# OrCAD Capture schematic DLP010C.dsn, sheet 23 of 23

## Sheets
23 PAGE 22 - UNUSED PINS: size Custom
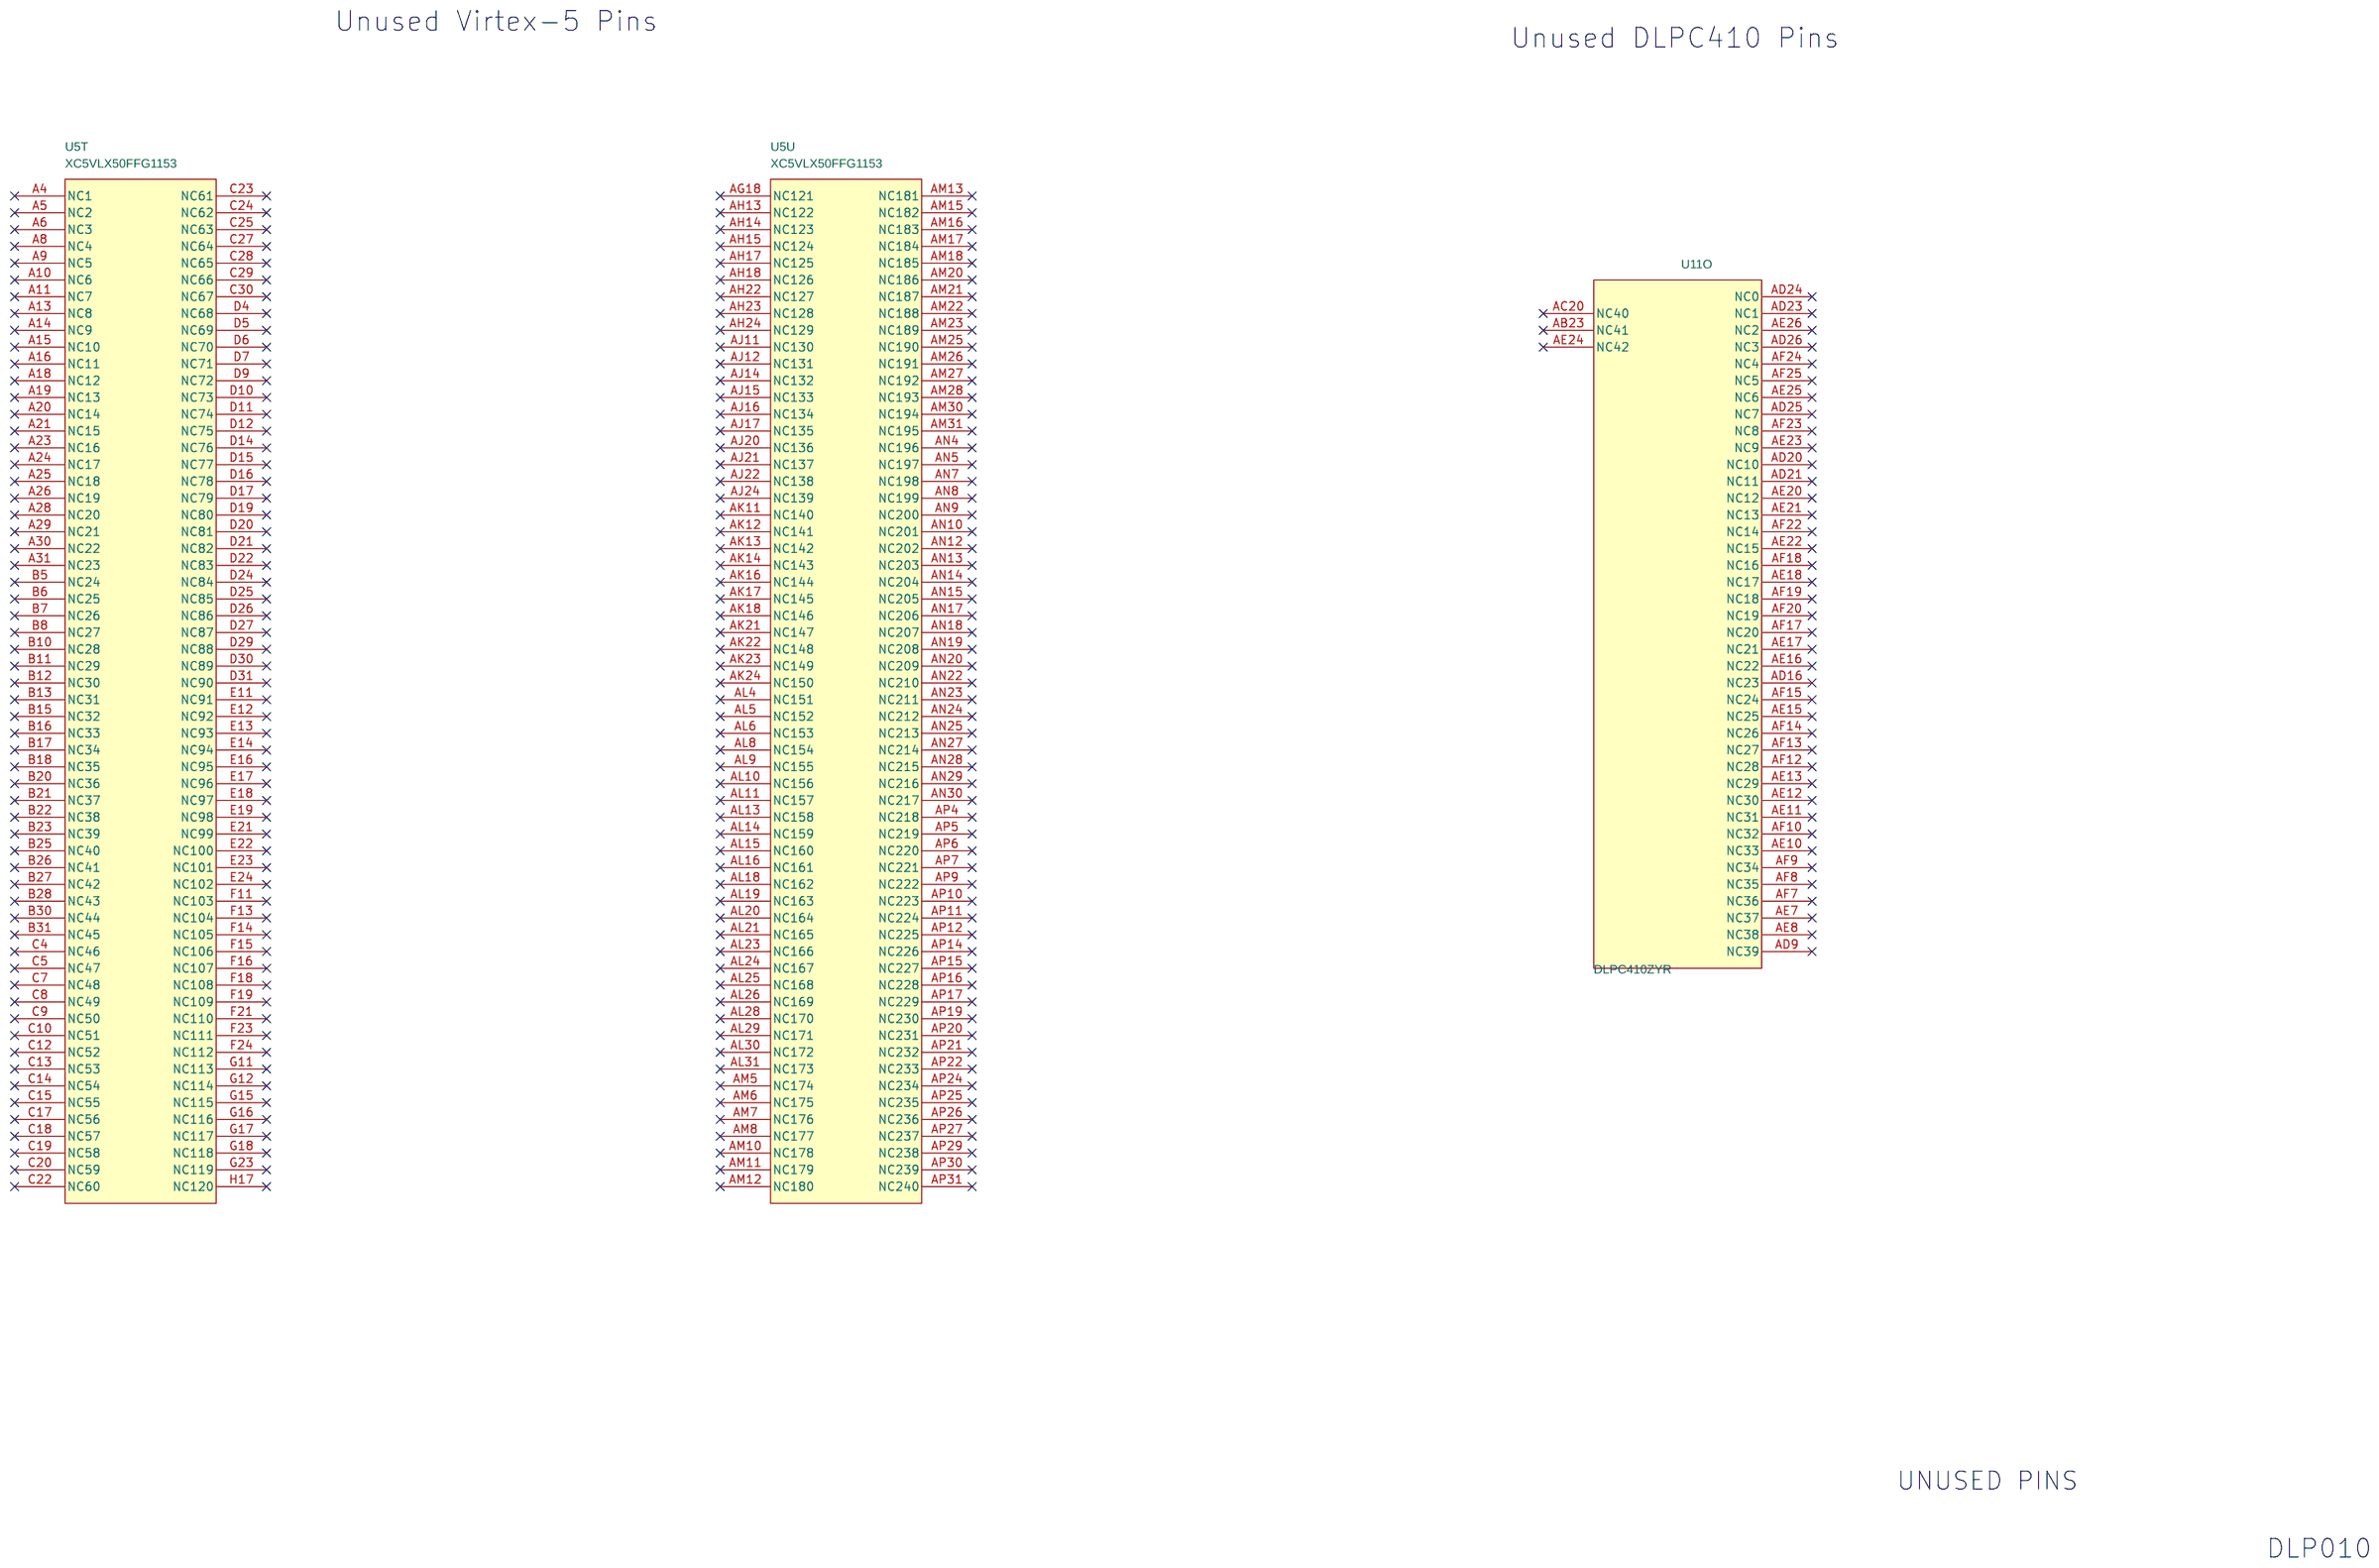
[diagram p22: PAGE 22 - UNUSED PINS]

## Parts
sheet PAGE 07 - VIRTEX5 - 4
U5  XC5VLX50FFG1153  [sm_ff1153]  (sections A,B,C,D,E,F,G,H,I,J,K,L,M,N,O,P,Q,R,S,T,U)
sheet PAGE 10 - DLPC410 - 2
U11  DLPC410ZYR  [sm_ff676]  (sections A,B,C,D,E,F,G,H,I,J,K,L,M,N,O)

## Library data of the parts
U5 = XC5VLX50FF1153_13: Manuf: xilinx; PartNumber: XC5VLX50-1FFG1153C; ROOM: V5
U11 = XC5VLX30FF676: Manuf: Texas Instruments; ROOM: DDC4100

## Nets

Not connected (* = marked no-connect by the designer): U5 A4(NC1)* A5(NC2)* A6(NC3)* A8(NC4)* A9(NC5)* A10(NC6)* A11(NC7)* A13(NC8)* A14(NC9)* A15(NC10)* A16(NC11)* A18(NC12)* A19(NC13)* A20(NC14)* A21(NC15)* A23(NC16)* A24(NC17)* A25(NC18)* A26(NC19)* A28(NC20)* A29(NC21)* A30(NC22)* A31(NC23)* AG18(NC121)* AH13(NC122)* AH14(NC123)* AH15(NC124)* AH17(NC125)* AH18(NC126)* AH22(NC127)* AH23(NC128)* AH24(NC129)* AJ11(NC130)* AJ12(NC131)* AJ14(NC132)* AJ15(NC133)* AJ16(NC134)* AJ17(NC135)* AJ20(NC136)* AJ21(NC137)* AJ22(NC138)* AJ24(NC139)* AK11(NC140)* AK12(NC141)* AK13(NC142)* AK14(NC143)* AK16(NC144)* AK17(NC145)* AK18(NC146)* AK21(NC147)* AK22(NC148)* AK23(NC149)* AK24(NC150)* AL4(NC151)* AL5(NC152)* AL6(NC153)* AL8(NC154)* AL9(NC155)* AL10(NC156)* AL11(NC157)* AL13(NC158)* AL14(NC159)* AL15(NC160)* AL16(NC161)* AL18(NC162)* AL19(NC163)* AL20(NC164)* AL21(NC165)* AL23(NC166)* AL24(NC167)* AL25(NC168)* AL26(NC169)* AL28(NC170)* AL29(NC171)* AL30(NC172)* AL31(NC173)* AM5(NC174)* AM6(NC175)* AM7(NC176)* AM8(NC177)* AM10(NC178)* AM11(NC179)* AM12(NC180)* AM13(NC181)* AM15(NC182)* AM16(NC183)* AM17(NC184)* AM18(NC185)* AM20(NC186)* AM21(NC187)* AM22(NC188)* AM23(NC189)* AM25(NC190)* AM26(NC191)* AM27(NC192)* AM28(NC193)* AM30(NC194)* AM31(NC195)* AN4(NC196)* AN5(NC197)* AN7(NC198)* AN8(NC199)* AN9(NC200)* AN10(NC201)* AN12(NC202)* AN13(NC203)* AN14(NC204)* AN15(NC205)* AN17(NC206)* AN18(NC207)* AN19(NC208)* AN20(NC209)* AN22(NC210)* AN23(NC211)* AN24(NC212)* AN25(NC213)* AN27(NC214)* AN28(NC215)* AN29(NC216)* AN30(NC217)* AP4(NC218)* AP5(NC219)* AP6(NC220)* AP7(NC221)* AP9(NC222)* AP10(NC223)* AP11(NC224)* AP12(NC225)* AP14(NC226)* AP15(NC227)* AP16(NC228)* AP17(NC229)* AP19(NC230)* AP20(NC231)* AP21(NC232)* AP22(NC233)* AP24(NC234)* AP25(NC235)* AP26(NC236)* AP27(NC237)* AP29(NC238)* AP30(NC239)* AP31(NC240)* B5(NC24)* B6(NC25)* B7(NC26)* B8(NC27)* B10(NC28)* B11(NC29)* B12(NC30)* B13(NC31)* B15(NC32)* B16(NC33)* B17(NC34)* B18(NC35)* B20(NC36)* B21(NC37)* B22(NC38)* B23(NC39)* B25(NC40)* B26(NC41)* B27(NC42)* B28(NC43)* B30(NC44)* B31(NC45)* C4(NC46)* C5(NC47)* C7(NC48)* C8(NC49)* C9(NC50)* C10(NC51)* C12(NC52)* C13(NC53)* C14(NC54)* C15(NC55)* C17(NC56)* C18(NC57)* C19(NC58)* C20(NC59)* C22(NC60)* C23(NC61)* C24(NC62)* C25(NC63)* C27(NC64)* C28(NC65)* C29(NC66)* C30(NC67)* D4(NC68)* D5(NC69)* D6(NC70)* D7(NC71)* D9(NC72)* D10(NC73)* D11(NC74)* D12(NC75)* D14(NC76)* D15(NC77)* D16(NC78)* D17(NC79)* D19(NC80)* D20(NC81)* D21(NC82)* D22(NC83)* D24(NC84)* D25(NC85)* D26(NC86)* D27(NC87)* D29(NC88)* D30(NC89)* D31(NC90)* E11(NC91)* E12(NC92)* E13(NC93)* E14(NC94)* E16(NC95)* E17(NC96)* E18(NC97)* E19(NC98)* E21(NC99)* E22(NC100)* E23(NC101)* E24(NC102)* F11(NC103)* F13(NC104)* F14(NC105)* F15(NC106)* F16(NC107)* F18(NC108)* F19(NC109)* F21(NC110)* F23(NC111)* F24(NC112)* G11(NC113)* G12(NC114)* G15(NC115)* G16(NC116)* G17(NC117)* G18(NC118)* G23(NC119)* H17(NC120)*; U11 AB23(NC41)* AC20(NC40)* AD9(NC39)* AD16(NC23)* AD20(NC10)* AD21(NC11)* AD23(NC1)* AD24(NC0)* AD25(NC7)* AD26(NC3)* AE7(NC37)* AE8(NC38)* AE10(NC33)* AE11(NC31)* AE12(NC30)* AE13(NC29)* AE15(NC25)* AE16(NC22)* AE17(NC21)* AE18(NC17)* AE20(NC12)* AE21(NC13)* AE22(NC15)* AE23(NC9)* AE24(NC42)* AE25(NC6)* AE26(NC2)* AF7(NC36)* AF8(NC35)* AF9(NC34)* AF10(NC32)* AF12(NC28)* AF13(NC27)* AF14(NC26)* AF15(NC24)* AF17(NC20)* AF18(NC16)* AF19(NC18)* AF20(NC19)* AF22(NC14)* AF23(NC8)* AF24(NC4)* AF25(NC5)*

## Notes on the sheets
sheet 23
- Unused Virtex-5 Pins
- Unused DLPC410 Pins
- UNUSED PINS
- DLP010
